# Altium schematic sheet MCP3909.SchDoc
size A4
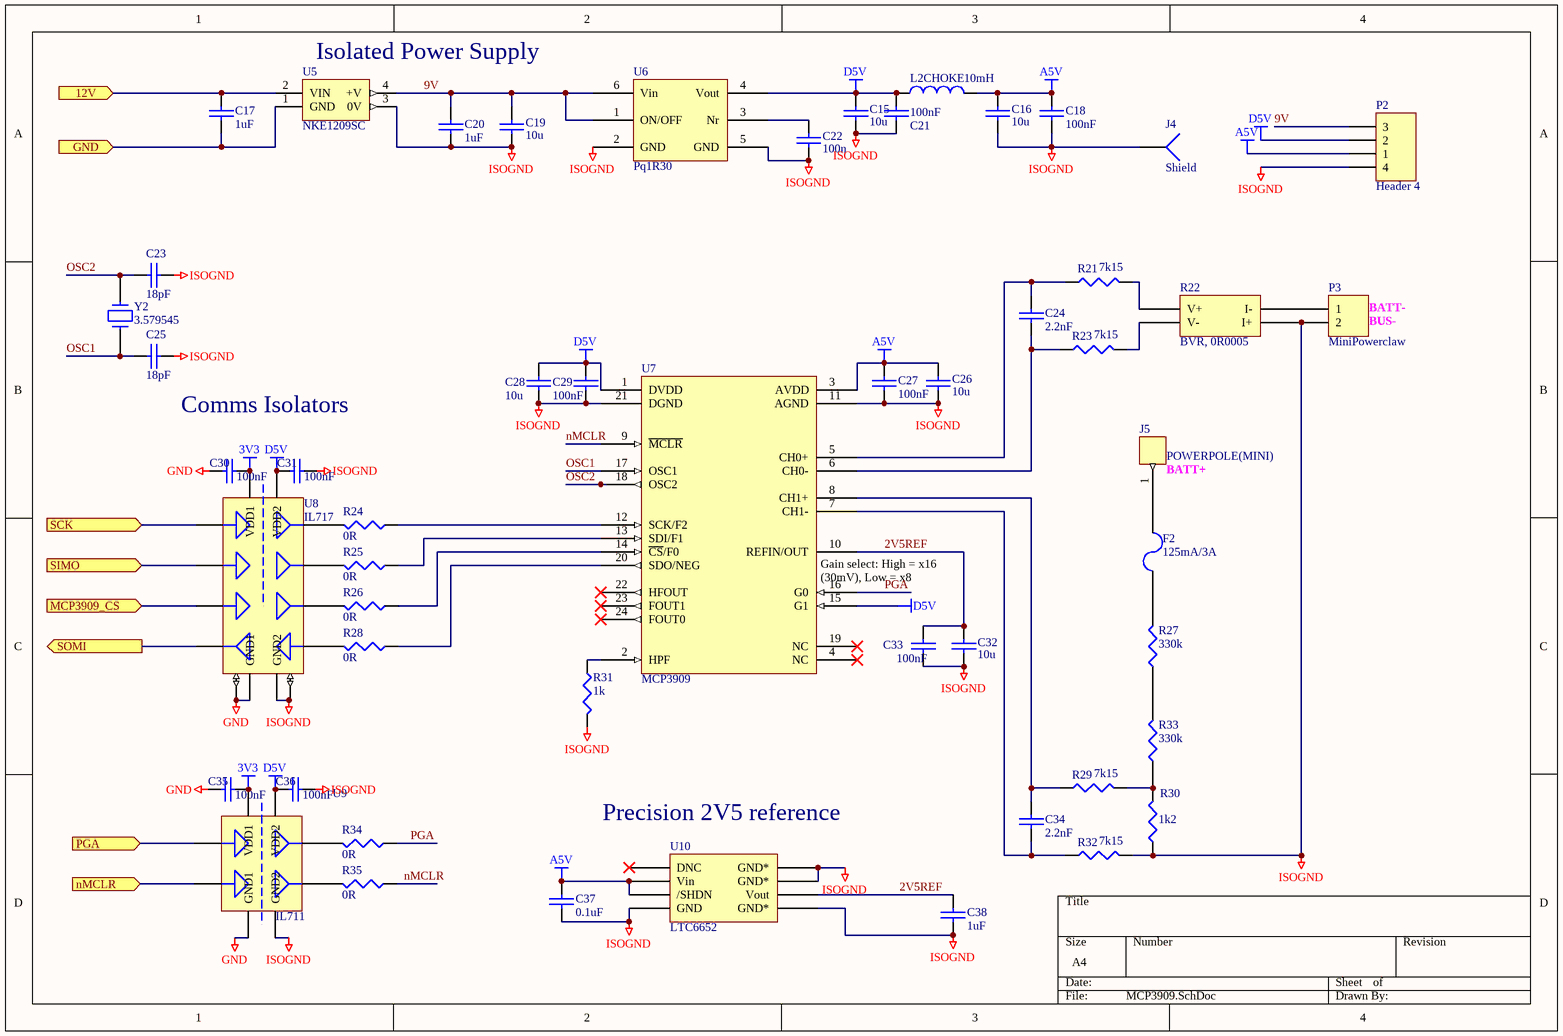
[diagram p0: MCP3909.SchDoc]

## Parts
C15  10u  [0805]
C16  10u  [0805]
C17  1uF  [0805]
C18  100nF  [0603]
C19  10u  [0805]
C20  1uF  [0805]
C21  100nF  [0603]
C22  100n  [0603]
C23  18pF  [0603]
C24  2.2nF  [0603]
C25  18pF  [0603]
C26  10u  [0805]
C27  100nF  [0603]
C28  10u  [0805]
C29  100nF  [0603]
C30  100nF  [0603]
C31  100nF  [0603]
C32  10u  [0805]
C33  100nF  [0603]
C34  2.2nF  [0603]
C35  100nF  [0603]
C36  100nF  [0603]
C37  0.1uF  [0805]
C38  1uF  [0805]
F2  125mA/3A  [LITTELFUSE-154-250V]
J4  Shield  [BMIS-203-SHIELD]
J5  POWERPOLE(MINI)  [POWERPOLE25A]
L2  CHOKE  value 10mH  [1812]
P2  Header 4  [HDR1X4]
P3  MiniPowerclaw  [MiniPowerpole-Hrz]
R21  7k15  [0603]
R22  BVR, 0R0005  [BVR]
R23  7k15  [0603]
R24  0R  [0603]
R25  0R  [0603]
R26  0R  [0603]
R27  330k  [1206]
R28  0R  [0603]
R29  7k15  [0603]
R30  1k2  [1206]
R31  1k  [0603]
R32  7k15  [0603]
R33  330k  [1206]
R34  0R  [0603]
R35  0R  [0603]
U5  NKE1209SC  [NPSIP4]
U6  Pq1R30  [SOT23-6]
U7  MCP3909  [SOP24-wide]
U8  IL717  [SO16]
U9  IL711  [SO8]
U10  LTC6652  [SOP8 - duplicate]
Y2  3.579545  [HC49/4H]

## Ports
12V (in), GND, MCP3909_CS (in), nMCLR (in), PGA (in), SCK (in), SIMO (in), SOMI (out)

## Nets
3V3: C30.2 C35.2 U8.1(VDD1) U9.1(VDD1)
A5V: C16.2 C18.1 C26.2 C27.1 C37.1 L2.2 P2.1 U7.3(AVDD) U10.2(Vin) U10.3(/SHDN)
D5V: C15.2 C21.1 C28.2 C29.2 C31.2 C36.2 L2.1 P2.2 U6.4(Vout) U7.1(DVDD) U7.15(G1) U8.16(VDD2) U9.8(VDD2)
GND: C30.1 C35.1 U8.2(GND1) U8.8(GND1) U9.4(GND1)
ISOGND: C15.1 C16.1 C18.2 C19.1 C20.2 C21.2 C22.1 C23.2 C25.2 C26.1 C27.2 C28.1 C29.1 C31.1 C32.1 C33.2 C36.1 C37.2 C38.1 J4.1 P2.4 P3.2 R22.4(I+) R30.1 R31.2 R32.2 U5.3(0V) U6.2(GND) U6.5(GND) U7.11(AGND) U7.21(DGND) U8.9(GND2) U8.15(GND2) U9.5(GND2) U10.4(GND) U10.5(GND*) U10.7(GND*) U10.8(GND*)
2V5REF: C32.2 C33.1 C38.2 U7.10(REFIN/OUT) U10.6(Vout)
9V: C19.2 C20.1 P2.3 U5.4(+V) U6.1(ON/OFF) U6.6(Vin)
12V: C17.1 U5.2(VIN) ; port 12V
GND: C17.2 U5.1(GND) ; port GND  [a separate net that carries the same name]
MCP3909_CS: U8.5(IN3) ; port MCP3909_CS
nMCLR: R35.1 U7.9(~{MCLR})
nMCLR: U9.3(IN2) ; port nMCLR  [a separate net that carries the same name]
OSC1: C25.1 U7.17(OSC1) Y2.1
OSC2: C23.1 U7.18(OSC2) Y2.2
PGA: R34.1 U7.16(G0)
PGA: U9.2(IN1) ; port PGA  [a separate net that carries the same name]
SCK: U8.3(IN1) ; port SCK
SIMO: U8.4(IN2) ; port SIMO
SOMI: U8.6(OUT4) ; port SOMI
NetC22_2: C22.2 U6.3(Nr)
NetC24_1: C24.1 R23.1 U7.6(CH0-)
NetC24_2: C24.2 R21.1 U7.5(CH0+)
NetC34_1: C34.1 R29.1 U7.8(CH1+)
NetC34_2: C34.2 R32.1 U7.7(CH1-)
NetF2_1: F2.1 R27.2
NetF2_2: F2.2 J5.1
NetP3_1: P3.1 R22.3(I-)
NetR21_2: R21.2 R22.1(V+)
NetR22_2: R22.2(V-) R23.2
NetR24_1: R24.1 U7.12(SCK/F2)
NetR24_2: R24.2 U8.14(OUT1)
NetR25_1: R25.1 U7.13(SDI/F1)
NetR25_2: R25.2 U8.13(OUT2)
NetR26_1: R26.1 U7.14(~{CS}/F0)
NetR26_2: R26.2 U8.12(OUT3)
NetR27_1: R27.1 R33.2
NetR28_1: R28.1 U7.20(SDO/NEG)
NetR28_2: R28.2 U8.11(IN4)
NetR29_2: R29.2 R30.2 R33.1
NetR31_1: R31.1 U7.2(HPF)
NetR34_2: R34.2 U9.7(OUT1)
NetR35_2: R35.2 U9.6(OUT2)

Not connected (* = marked no-connect by the designer): U7 4(NC)* 19(NC)* 22(HFOUT)* 23(FOUT1)* 24(FOUT0)*; U10 1(DNC)*

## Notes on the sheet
- (near U5) Isolated Power Supply
- (near P3) BATT-
- (near P3) BUS-
- Comms Isolators
- (near J5) BATT+
- (near U7) Gain select: High = x16 (30mV), Low = x8 (60mV)
- (near U10) Precision 2V5 reference

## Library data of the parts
C15 C16 C19 C22 C26 C28 C32 = CAP: Capacitor; Order#: 521-2820
C17 C20 C37 C38 = CAP: Capacitor; Order#: ??
C18 C21 C27 C29-C31 C33 C35 C36 = CAP: Capacitor; Order#: 753-567
C23 C25 = CAP: Capacitor; Order#: 721-992
C24 C34 = CAP: Capacitor; Order#: 498-592
F2 = FUSE2: Fuse; Order#: 994-3609
J4 = Socket
J5 = CON1: RS: 534-979 + 534-963
L2 = INDUCTOR: Manufacturer: Generic Components; Class I: Passive
P2 = Header 4: Header, 4-Pin
P3 = Header 2: Header, 2-Pin; pin to pad: 1>2 2>1
R21 R23 R29 R31 R32 = RES1: Resistor; Order#: 933-1697
R22 = BVR
R24-R26 R28 R34 R35 = RES1: Resistor; Order#: 9233253
R27 R33 = RES1: Order#: 308-9587
R30 = RES1: Resistor; Value: 0.002; Order#: BVS-A-R002
U5 = LME1209S: Isolated 250mW Single Output; RS: 689-5034
U7 = MCP3909: Energy Measurement IC; Order#: MCP3909-I/SS-ND
U8 = IL717: Isoloop IL717 - www.nve.com; Order#: 957-0659
U9 = IL711: IL711 Optical Isolator; Order#: 1314985
Y2 = CRYSTAL: Order#: 971-2895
